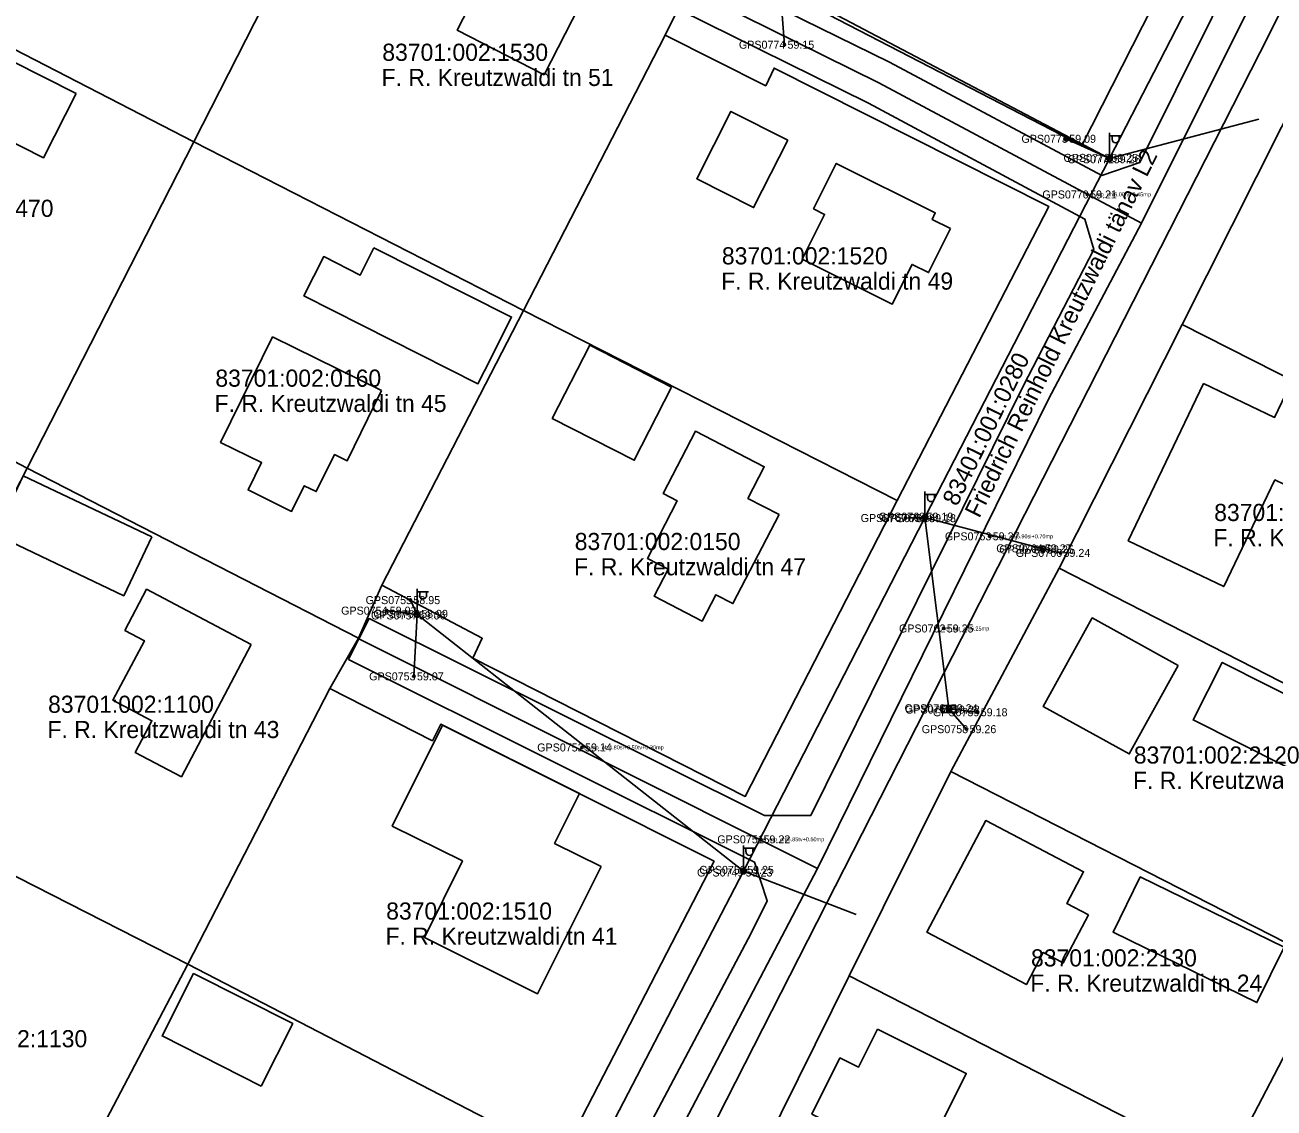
# Model space of a CAD drawing. Extents: x 580119 to 583377, y 6518915 to 6520820.
# Drawn here: x 581663.4 to 581772.7, y 6520360.6 to 6520455.4 of the extents above; entities that cross this region are included whole.
import ezdxf

# ---------------------------------------------------------------- set-up
doc = ezdxf.new("R2010")
doc.units = 0
for name, color, linetype in [('ELRAJATISMP', 7, 'Continuous'), ('Hoone Elu- või ühiskondlik hoone', 7, 'Continuous'), ('Hoone Kõrval- või tootmishoone', 7, 'Continuous'), ('L_AADRESS', 7, 'Continuous'), ('MOOTKORG-EH2000', 7, 'Continuous'), ('MOOTMPUNKT', 7, 'Continuous'), ('MOOTNR', 7, 'Continuous'), ('MPOHULIIN', 7, 'Continuous'), ('PIIR', 7, 'Continuous'), ('POST', 7, 'Continuous'), ('Rippe kõrgus', 7, 'Continuous'), ('SIOHULIIN', 7, 'Continuous'), ('Tee Liiklusala', 7, 'Continuous'), ('Tee Tänav Kruuskate', 7, 'Continuous'), ('Tee Tänav Püsikate', 7, 'Continuous'), ('TUNNUS', 7, 'Continuous')]:
    doc.layers.add(name, color=color, linetype=linetype)

msp = doc.modelspace()

# ---------------------------------------------------------------- linework, layer by layer
at = {"layer": 'ELRAJATISMP'}
for p, q in [((581744.08, 6520395.83), (581744.08, 6520395.23)), ((581744.35, 6520395.83), (581744.35, 6520395.23))]:
    msp.add_line(p, q, dxfattribs=at)
msp.add_lwpolyline([(581743.62, 6520395.83), (581744.81, 6520395.83), (581744.81, 6520395.23), (581743.62, 6520395.23)], close=True, dxfattribs=at)
at = {"layer": 'Hoone Elu- või ühiskondlik hoone'}
for points in [[(581712.49, 6520458.2), (581708.81, 6520451.01), (581701.22, 6520454.9), (581704.89, 6520462.09)], [(581744.35, 6520437.55), (581742.44, 6520433.71), (581740.99, 6520434.42), (581739.26, 6520430.95), (581731.39, 6520434.89), (581733.35, 6520438.8), (581732.38, 6520439.29), (581734.37, 6520443.26), (581743.03, 6520438.93), (581742.74, 6520438.36)], [(581694.6, 6520423.38), (581691.59, 6520417.25), (581690.48, 6520417.79), (581688.88, 6520414.54), (581687.84, 6520415.05), (581686.73, 6520412.81), (581682.92, 6520414.69), (581684.1, 6520417.09), (581680.52, 6520418.85), (581685.06, 6520428.08)], [(581766.49, 6520424.01), (581772.7, 6520421.03), (581774.02, 6520423.77), (581780.39, 6520420.71), (581776.95, 6520413.54), (581772.73, 6520415.56), (581768.25, 6520406.24), (581759.9, 6520410.25)], [(581729.37, 6520412.54), (581725.33, 6520404.75), (581723.84, 6520405.52), (581722.65, 6520403.21), (581718.44, 6520405.39), (581719.66, 6520407.75), (581717.85, 6520408.7), (581720.45, 6520413.74), (581719.23, 6520414.37), (581722.05, 6520419.82), (581728.06, 6520416.72), (581726.64, 6520413.95)], [(581683.2, 6520401.18), (581677.09, 6520389.6), (581673.05, 6520391.73), (581674.51, 6520394.5), (581671.1, 6520396.29), (581673.85, 6520401.49), (581672.15, 6520402.4), (581674.05, 6520406)], [(581764.28, 6520399.34), (581759.99, 6520391.59), (581752.46, 6520395.75), (581756.76, 6520403.5)], [(581713.79, 6520381.75), (581708.24, 6520370.61), (581698.34, 6520375.54), (581701.67, 6520382.23), (581695.53, 6520385.28), (581699.92, 6520394.1), (581711.9, 6520388.14), (581709.73, 6520383.76)], [(581756.42, 6520377.51), (581754.22, 6520373.31), (581752.47, 6520374.23), (581750.99, 6520371.41), (581742.29, 6520375.99), (581747.44, 6520385.77), (581756, 6520381.28), (581754.54, 6520378.5)], [(581737.98, 6520367.52), (581745.74, 6520363.64), (581741.64, 6520355.41), (581732.24, 6520360.09), (581734.69, 6520365), (581736.31, 6520364.19)]]:
    msp.add_lwpolyline(points, close=True, dxfattribs=at)
at = {"layer": 'Hoone Kõrval- või tootmishoone'}
for points in [[(581667.88, 6520449.36), (581665.02, 6520443.73), (581653.75, 6520449.45), (581656.6, 6520455.07)], [(581730.12, 6520445.28), (581727.14, 6520439.39), (581722.16, 6520441.91), (581725.15, 6520447.8)], [(581693.93, 6520435.88), (581705.97, 6520429.81), (581703.59, 6520425.1), (581703.02, 6520423.98), (581687.81, 6520431.67), (581689.54, 6520435.11), (581692.73, 6520433.49)], [(581719.96, 6520423.69), (581716.69, 6520417.28), (581709.53, 6520420.94), (581712.8, 6520427.35)], [(581674.5, 6520410.58), (581672.05, 6520405.43), (581660.8, 6520410.78), (581663.24, 6520415.93)], [(581780.11, 6520393.55), (581777.57, 6520388.54), (581765.58, 6520394.57), (581768.12, 6520399.6)], [(581773.53, 6520374.68), (581771.16, 6520369.84), (581758.58, 6520375.99), (581760.95, 6520380.84)], [(581684.08, 6520362.54), (581675.4, 6520366.92), (581678.15, 6520372.38), (581686.83, 6520368.01)]]:
    msp.add_lwpolyline(points, close=True, dxfattribs=at)
at = {"layer": 'MOOTMPUNKT'}
for centre in [(581729.84, 6520453.64), (581754.48, 6520445.41), (581758.16, 6520443.74), (581758.37, 6520443.62), (581756.31, 6520440.54), (581740.42, 6520412.23), (581742, 6520412.35), (581742.23, 6520412.22), (581747.79, 6520410.63), (581752.35, 6520409.58), (581752.54, 6520409.48), (581753.98, 6520409.18), (581697.12, 6520405.05), (581695.05, 6520404.13), (581697.6, 6520403.71), (581697.8, 6520403.85), (581743.77, 6520402.57), (581697.43, 6520398.38), (581744.12, 6520395.59), (581744.31, 6520395.47), (581746.74, 6520395.24), (581745.76, 6520393.76), (581712.13, 6520392.16), (581727.74, 6520384.12), (581726.31, 6520381.45), (581726.18, 6520381.22)]:
    msp.add_circle(centre, 0.1, dxfattribs=at)
at = {"layer": 'MPOHULIIN'}
for p, q in [((581758.27, 6520443.68), (581771.83, 6520470.07)), ((581758.27, 6520443.68), (581742.11, 6520412.29)), ((581744.22, 6520395.53), (581742.11, 6520412.29)), ((581745.76, 6520393.76), (581744.22, 6520395.53)), ((581746.74, 6520395.24), (581744.22, 6520395.53))]:
    msp.add_line(p, q, dxfattribs=at)
for points in [[(581758.27, 6520443.68), (581729.42, 6520458.87), (581729.84, 6520453.64)], [(581710.72, 6520351.41), (581726.25, 6520381.34), (581742.11, 6520412.29)], [(581753.98, 6520409.18), (581752.44, 6520409.53), (581742.11, 6520412.29), (581740.42, 6520412.23)], [(581697.43, 6520398.38), (581697.7, 6520403.78), (581697.12, 6520405.05)], [(581726.25, 6520381.34), (581697.7, 6520403.78), (581695.05, 6520404.13)]]:
    msp.add_lwpolyline(points, dxfattribs=at)
at = {"layer": 'PIIR'}
for points in [[(581662.65, 6520485.99), (581665.21, 6520491.23), (581694.15, 6520476.35), (581692.6, 6520473.48), (581678.18, 6520445.13), (581649.42, 6520460)], [(581732.69, 6520458.86), (581724.02, 6520463.6), (581736.97, 6520489.11), (581738.55, 6520488.21), (581769.1, 6520470.95), (581755.83, 6520444.83), (581731.9, 6520457.2)], [(581692.6, 6520473.48), (581721.62, 6520459.01), (581719.39, 6520454.49), (581707.01, 6520430.4), (581678.18, 6520445.13)], [(581637.33, 6520435.93), (581649.42, 6520460), (581678.18, 6520445.13), (581663.6, 6520416.58), (581634.87, 6520431.66)], [(581719.39, 6520454.49), (581728.2, 6520450.05), (581728.92, 6520451.6), (581752.96, 6520439.48), (581739.69, 6520413.76), (581707.01, 6520430.4)], [(581775.47, 6520450.71), (581802.33, 6520436.92), (581791.42, 6520415.56), (581764.63, 6520429.16)], [(581678.18, 6520445.13), (581707.01, 6520430.4), (581694.63, 6520406.35), (581692.57, 6520401.72), (581663.6, 6520416.58)], [(581632.47, 6520426.94), (581634.87, 6520431.66), (581663.6, 6520416.58), (581648.92, 6520388.04), (581633.24, 6520396.27), (581620.3, 6520402.87)], [(581703.4, 6520401.71), (581694.63, 6520406.35), (581707.01, 6520430.4), (581739.69, 6520413.76), (581726.4, 6520387.87), (581702.59, 6520399.97)], [(581764.63, 6520429.16), (581791.42, 6520415.56), (581791.17, 6520415.07), (581780.5, 6520394.2), (581753.86, 6520407.85)], [(581648.92, 6520388.04), (581663.6, 6520416.58), (581692.57, 6520401.72), (581690.07, 6520397.32), (581677.65, 6520373.21), (581655.37, 6520384.54)], [(581753.86, 6520407.85), (581780.5, 6520394.2), (581786.84, 6520390.94), (581785.47, 6520388.28), (581777.64, 6520373.06), (581744.38, 6520390.07)], [(581690.07, 6520397.32), (581699.05, 6520392.74), (581699.77, 6520394.19), (581723.68, 6520382.21), (581710.31, 6520356.3), (581677.65, 6520373.21)], [(581744.38, 6520390.07), (581777.64, 6520373.06), (581769.84, 6520358.07), (581768.32, 6520355.34), (581735.49, 6520372.19)], [(581769.84, 6520358.07), (581777.64, 6520373.06), (581785.47, 6520388.28), (581801.36, 6520378.94), (581785.35, 6520349.14), (581782.27, 6520350.98), (581774.1, 6520355.46)], [(581655.37, 6520384.54), (581677.65, 6520373.21), (581663.75, 6520346.68), (581641.44, 6520358.2)], [(581677.65, 6520373.21), (581710.31, 6520356.3), (581696.78, 6520330.58), (581663.75, 6520346.68)], [(581726.57, 6520354.16), (581735.49, 6520372.19), (581768.32, 6520355.34), (581759.06, 6520337.58)]]:
    msp.add_lwpolyline(points, close=True, dxfattribs=at)
for points in [[(581731.9, 6520457.2), (581755.83, 6520444.83), (581769.1, 6520470.95)], [(581775.47, 6520450.71), (581764.63, 6520429.16), (581753.86, 6520407.85), (581744.38, 6520390.07), (581735.49, 6520372.19), (581726.57, 6520354.16), (581710.47, 6520322.41), (581696.78, 6520330.58), (581710.31, 6520356.3), (581723.68, 6520382.21), (581699.77, 6520394.19), (581699.05, 6520392.74), (581690.07, 6520397.32), (581692.57, 6520401.72), (581694.63, 6520406.35), (581703.4, 6520401.71), (581702.59, 6520399.97), (581726.4, 6520387.87), (581739.69, 6520413.76), (581752.96, 6520439.48), (581728.92, 6520451.6), (581728.2, 6520450.05), (581719.39, 6520454.49), (581721.62, 6520459.01)]]:
    msp.add_lwpolyline(points, dxfattribs=at)
at = {"layer": 'POST'}
for p, q in [((581758.27, 6520443.93), (581758.27, 6520445.93)), ((581758.27, 6520445.68), (581759.27, 6520445.68)), ((581758.49, 6520445.36), (581758.49, 6520445.68)), ((581759.1, 6520445.36), (581759.1, 6520445.68)), ((581758.27, 6520443.68), (581758.27, 6520443.68)), ((581742.11, 6520412.54), (581742.11, 6520414.54)), ((581742.11, 6520414.29), (581743.11, 6520414.29)), ((581742.34, 6520413.97), (581742.34, 6520414.29)), ((581742.95, 6520413.97), (581742.95, 6520414.29)), ((581742.11, 6520412.29), (581742.11, 6520412.29)), ((581697.7, 6520404.03), (581697.7, 6520406.03)), ((581697.7, 6520405.78), (581698.7, 6520405.78)), ((581697.93, 6520405.46), (581697.93, 6520405.78)), ((581698.54, 6520405.46), (581698.54, 6520405.78)), ((581697.7, 6520403.78), (581697.7, 6520403.78)), ((581726.25, 6520381.59), (581726.25, 6520383.59)), ((581726.25, 6520383.34), (581727.25, 6520383.34)), ((581726.47, 6520383.02), (581726.47, 6520383.34)), ((581727.08, 6520383.02), (581727.08, 6520383.34)), ((581726.25, 6520381.34), (581726.25, 6520381.34))]:
    msp.add_line(p, q, dxfattribs=at)
msp.add_lwpolyline([(581754.48, 6520445.41), (581758.27, 6520443.68)], dxfattribs=at)
for centre, radius in [((581754.48, 6520445.41), 0.2), ((581758.27, 6520443.68), 0.25), ((581742.11, 6520412.29), 0.25), ((581752.44, 6520409.53), 0.25), ((581697.7, 6520403.78), 0.25), ((581744.22, 6520395.53), 0.25), ((581726.25, 6520381.34), 0.25)]:
    msp.add_circle(centre, radius, dxfattribs=at)
for centre in [(581758.8, 6520445.36), (581742.65, 6520413.97), (581698.23, 6520405.46), (581726.78, 6520383.02)]:
    msp.add_arc(centre, 0.306, 180, 0, dxfattribs=at)
at = {"layer": 'SIOHULIIN'}
for points in [[(581771.32, 6520447.12), (581758.27, 6520443.68), (581729.42, 6520458.87)], [(581736.11, 6520377.55), (581726.25, 6520381.34), (581697.7, 6520403.78)]]:
    msp.add_lwpolyline(points, dxfattribs=at)
at = {"layer": 'Tee Liiklusala'}
for points in [[(581722.38, 6520460.32), (581739.01, 6520452.1), (581757.59, 6520442.21), (581760.92, 6520443.35), (581789.38, 6520500.55)], [(581793.32, 6520496.68), (581771.4, 6520452.94), (581722.41, 6520356.7), (581707.77, 6520328.5), (581706.7, 6520325.22), (581706.57, 6520323.24), (581706.96, 6520321.16), (581707.86, 6520319.73), (581708.97, 6520318.47), (581787.03, 6520271.32)], [(581634.54, 6520359.01), (581694.54, 6520327.56), (581697.45, 6520327.01), (581699.85, 6520327.5), (581702.06, 6520328.93), (581726.93, 6520375.92), (581728.32, 6520378.73), (581727.22, 6520382.12), (581691.71, 6520399.86), (581692.6, 6520401.65), (581693.5, 6520403.43), (581728.08, 6520386.2), (581732.14, 6520386.2), (581750.71, 6520423.77), (581756.89, 6520435.72), (581756.1, 6520438.38), (581737.18, 6520448.54), (581720.6, 6520456.73)]]:
    msp.add_lwpolyline(points, dxfattribs=at)
at = {"layer": 'Tee Tänav Kruuskate'}
msp.add_lwpolyline([(581761.06, 6520438.04), (581738.09, 6520450.32), (581721.49, 6520458.52)], dxfattribs=at)
at = {"layer": 'Tee Tänav Püsikate'}
for points in [[(581794.85, 6520508.84), (581789.9, 6520495.76), (581761.06, 6520438.04)], [(581761.06, 6520438.04), (581752.94, 6520422.63), (581732.72, 6520381.57)], [(581732.72, 6520381.57), (581692.6, 6520401.65)], [(581700.8, 6520320.68), (581732.72, 6520381.57)]]:
    msp.add_lwpolyline(points, dxfattribs=at)

# ---------------------------------------------------------------- texts
at = {"layer": 'L_AADRESS'}
for s, p in [('F. R. Kreutzwaldi tn 51', (581694.6, 6520450.03)), ('F. R. Kreutzwaldi tn 49', (581724.3, 6520432.21)), ('F. R. Kreutzwaldi tn 45', (581679.99, 6520421.51)), ('F. R. Kreutzwaldi tn 28', (581767.35, 6520409.77)), ('F. R. Kreutzwaldi tn 47', (581711.43, 6520407.22)), ('F. R. Kreutzwaldi tn 43', (581665.37, 6520392.98)), ('F. R. Kreutzwaldi tn 26', (581760.32, 6520388.54)), ('F. R. Kreutzwaldi tn 41', (581694.94, 6520374.9)), ('F. R. Kreutzwaldi tn 24', (581751.34, 6520370.79))]:
    msp.add_text(s, height=1.5, dxfattribs=at).set_placement(p)
msp.add_text('Friedrich Reinhold Kreutzwaldi tänav L2', height=1.5, rotation=63.8568, dxfattribs=at).set_placement((581746.88, 6520412.16))
at = {"layer": 'MOOTKORG-EH2000'}
for s, p in [(' 59.15', (581729.84, 6520453.29)), (' 59.09', (581754.48, 6520445.06)), (' 59.25', (581758.16, 6520443.39)), (' 59.26', (581758.37, 6520443.27)), (' 59.21', (581756.31, 6520440.19)), (' 59.14', (581740.42, 6520411.88)), (' 59.19', (581742, 6520412)), (' 59.18', (581742.23, 6520411.87)), (' 59.27', (581747.79, 6520410.28)), (' 59.27', (581752.35, 6520409.23)), (' 59.25', (581752.54, 6520409.13)), (' 59.24', (581753.98, 6520408.83)), (' 59.02', (581695.05, 6520403.78)), (' 58.95', (581697.12, 6520404.7)), (' 59.06', (581697.6, 6520403.36)), (' 58.99', (581697.8, 6520403.5)), (' 59.25', (581743.77, 6520402.22)), (' 59.07', (581697.43, 6520398.03)), (' 59.24', (581744.12, 6520395.24)), (' 59.22', (581744.31, 6520395.12)), (' 59.18', (581746.74, 6520394.89)), (' 59.26', (581745.76, 6520393.41)), (' 59.14', (581712.13, 6520391.81)), (' 59.22', (581727.74, 6520383.77)), (' 59.23', (581726.18, 6520380.87)), (' 59.25', (581726.31, 6520381.1))]:
    msp.add_text(s, height=0.7, dxfattribs=at).set_placement(p)
at = {"layer": 'MOOTNR'}
for s, p in [('GPS0774 ', (581725.85, 6520453.29)), ('GPS0773 ', (581750.56, 6520445.06)), ('GPS0772 ', (581754.24, 6520443.39)), ('GPS0771 ', (581754.59, 6520443.27)), ('GPS0770 ', (581752.39, 6520440.19)), ('GPS0767 ', (581736.5, 6520411.88)), ('GPS0768 ', (581738.08, 6520412)), ('GPS0769 ', (581738.31, 6520411.87)), ('GPS0763 ', (581743.87, 6520410.28)), ('GPS0764 ', (581748.36, 6520409.23)), ('GPS0765 ', (581748.62, 6520409.13)), ('GPS0766 ', (581750.06, 6520408.83)), ('GPS0754 ', (581691.06, 6520403.78)), ('GPS0755 ', (581693.2, 6520404.7)), ('GPS0757 ', (581693.68, 6520403.36)), ('GPS0756 ', (581693.88, 6520403.5)), ('GPS0762 ', (581739.85, 6520402.22)), ('GPS0753 ', (581693.51, 6520398.03)), ('GPS0761 ', (581740.34, 6520395.24)), ('GPS0760 ', (581740.39, 6520395.12)), ('GPS0759 ', (581742.82, 6520394.89)), ('GPS0758 ', (581741.84, 6520393.41)), ('GPS0752 ', (581708.21, 6520391.81)), ('GPS0751 ', (581723.96, 6520383.77)), ('GPS0749 ', (581722.19, 6520380.87)), ('GPS0750 ', (581722.39, 6520381.1))]:
    msp.add_text(s, height=0.7, dxfattribs=at).set_placement(p)
at = {"layer": 'Rippe kõrgus'}
for s, p in [(' el_mp_ohl6.00tv+0.45mp', (581756.31, 6520440.37)), (' el_mp_ohl5.90si+0.70mp', (581747.79, 6520410.46)), (' el_mp_ohl6.25mp', (581743.77, 6520402.39)), (' el_mp_ohl4.80si+0.50tv+0.30mp', (581712.13, 6520391.99)), (' el_mp_ohl6.85tv+0.50mp', (581727.74, 6520383.95))]:
    msp.add_text(s, height=0.35, dxfattribs=at).set_placement(p)
at = {"layer": 'TUNNUS'}
for s, p in [('83701:002:1530', (581694.66, 6520452.23)), ('83701:002:1470', (581651.4, 6520438.58)), ('83701:002:1520', (581724.36, 6520434.42)), ('83701:002:0160', (581680.06, 6520423.72)), ('83701:002:2110', (581767.42, 6520411.97)), ('83701:002:0150', (581711.49, 6520409.43)), ('83701:002:1100', (581665.43, 6520395.19)), ('83701:002:2120', (581760.39, 6520390.75)), ('83701:002:1510', (581695, 6520377.1)), ('83701:002:2130', (581751.4, 6520373)), ('83701:002:1130', (581654.35, 6520365.93))]:
    msp.add_text(s, height=1.5, dxfattribs=at).set_placement(p)
msp.add_text('83401:001:0280', height=1.5, rotation=63.8568, dxfattribs=at).set_placement((581744.93, 6520413.19))

doc.saveas('drawing.dxf')
